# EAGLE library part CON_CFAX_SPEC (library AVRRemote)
PIN HEADER
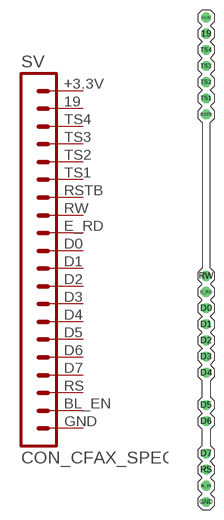
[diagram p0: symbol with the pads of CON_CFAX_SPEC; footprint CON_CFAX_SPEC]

Designator prefix SV

## CON_CFAX_SPEC  [CON_CFAX_SPEC]
19  19  pas
+3.3V  20  pas
BL_EN  2  pas
D0  11  pas
D1  10  pas
D2  9  pas
D3  8  pas
D4  7  pas
D5  6  pas
D6  5  pas
D7  4  pas
E_RD  12  pas
GND  1  pas
RS  3  pas
RSTB  14  pas
RW  13  pas
TS1  15  pas
TS2  16  pas
TS3  17  pas
TS4  18  pas

## Footprint CON_CFAX_SPEC (pad centres in mm)
PIN HEADER
drill 1.016 octagon: 19 1.27,50.8; +3.3V 1.27,53.34; BL_EN 1.27,-20.32; D0 1.27,7.62; D1 1.27,5.08; D2 1.27,2.54; D3 1.27,0; D4 1.27,-2.54; D5 1.27,-7.62; D6 1.27,-10.16; D7 1.27,-15.24; E_RD 1.27,10.16; GND 1.27,-22.86; RS 1.27,-17.78; RSTB 1.27,38.1; RW 1.27,12.7; TS1 1.27,40.64; TS2 1.27,43.18; TS3 1.27,45.72; TS4 1.27,48.26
